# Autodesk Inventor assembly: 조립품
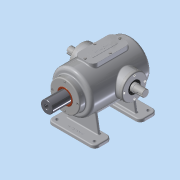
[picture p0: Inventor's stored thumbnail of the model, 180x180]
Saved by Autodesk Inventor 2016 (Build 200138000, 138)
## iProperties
Created: 2018-11
Part Number: 조립품
Material: 일반
Document SubType Name: Assembly
Designer: user
Mass: 8191.31 g
Surface Area: 4241.88 cm^2
Volume: 1855.5 cm^3
Density: 4.4146 g/cm^3
Author: user
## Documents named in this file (15)
- C:\Users\user\Desktop\381121V1003\조립품.iam
- C:\Users\user\Desktop\381121V1003\가변스프링.ipt
- C:\Users\user\Desktop\381121V1003\베어링 6205.ipt
- 베어링 6205.ipt
- C:\Users\user\Desktop\381121V1003\본체.ipt
- C:\Users\user\Desktop\381121V1003\볼트 M4x0.7.ipt
- C:\Users\user\Desktop\381121V1003\부시.ipt
- C:\Users\user\Desktop\381121V1003\상부커버.ipt
- C:\Users\user\Desktop\381121V1003\슬라이드 커버.ipt
- C:\Users\user\Desktop\381121V1003\슬라이드.ipt
- C:\Users\user\Desktop\381121V1003\오일실.ipt
- 오일실.ipt
- C:\Users\user\Desktop\381121V1003\육각머리볼트 M4.ipt
- C:\Users\user\Desktop\381121V1003\축 커버.ipt
- C:\Users\user\Desktop\381121V1003\편심축.ipt
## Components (13 placed, 2 different names)
1. 가변스프링:1
2. M4x0.7:1
3. M4x0.7:3
4. M4x0.7:4
5. M4x0.7:5
6. M4x0.7:2
7. M4x0.7:6
8. M4x0.7:7
9. M4x0.7:8
10. M4x0.7:9
11. M4x0.7:10
12. M4x0.7:11
13. M4x0.7:12
